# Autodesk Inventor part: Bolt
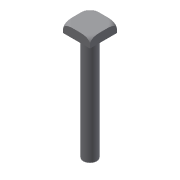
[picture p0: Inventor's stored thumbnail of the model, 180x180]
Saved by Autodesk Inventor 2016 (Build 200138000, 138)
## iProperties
Created: 2009-04
Part Number: Bolt
Document SubType Name: Modeling
Designer: Sham
Density: 1 g/cm^3
Material: Generic
Appearance: Default
Author: Sham
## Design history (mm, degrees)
sketch "Sketch1"
  geometry: L1 (-12, 12)-(12, 12); L2 (12, 12)-(12, -12); L3 (12, -12)-(-12, -12); L4 (-12, -12)-(-12, 12); 1 further point
  constraints: 8 end point, 2 parallel, 2 perpendicular, 1 horizontal, 1 other
  dimensions: "d0" = 24 distance of L1.start L1.end; "d1" = 12 distance from line of L2 point (0, 0); "d2" = 12 distance from line of L1 point (0, 0)
extrude "Extrusion1" new body sketch "Sketch1" distance "d3" = 8; taper "d4" = 0 deg
sketch "Sketch2"
  geometry: C1 r 6 at (0, 0)
  constraints: 1 centre point
  dimensions: "d5" = 12 diameter of C1
extrude "Extrusion2" join sketch "Sketch2" distance "d6" = 96; taper "d7" = 0 deg
workpoint "Work Point1"
workplane "Work Plane1"
sketch "Sketch3"
  geometry: L1 (33.941, 5)-(33.941, 6); L2 (28.941, 0)-(28.405, 0); L3 (16.971, 125.007)-(16.971, -22.043) reference; A1 r 5 centre (28.941, 5) between (28.941, 0) and (33.941, 5); 1 further point
  constraints: 4 end point, 2 point on circle, 2 point on line, 2 tangent, 1 centre point, 1 perpendicular
  dimensions: "d10" = 5 radius of A1
revolve "Revolution1" sketch "Sketch3" stored, may be unused: angle "d12" = 90 deg
body "Solid1"
other parameters: "d11" = 90 deg
